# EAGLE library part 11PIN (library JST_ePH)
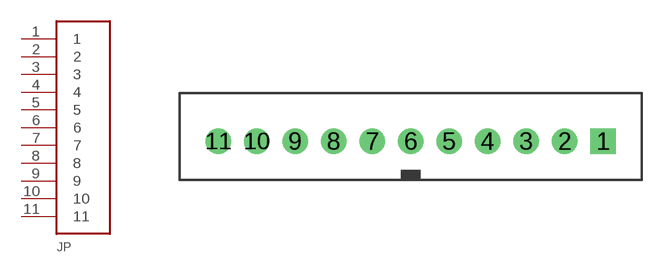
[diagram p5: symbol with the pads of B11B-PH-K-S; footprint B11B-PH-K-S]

Designator prefix JP

## 11PIN  [B11B-PH-K-S]
1  1
2  2
3  3
4  4
5  5
6  6
7  7
8  8
9  9
10  10
11  11

## Footprint B11B-PH-K-S (pad centres in mm)
drill 0.813 square: 1 10,0
drill 0.813 round: 2 8,0; 3 6,0; 4 4,0; 5 2,0; 6 0,0; 7 -2,0; 8 -4,0; 9 -6,0; 10 -8,0; 11 -10,0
